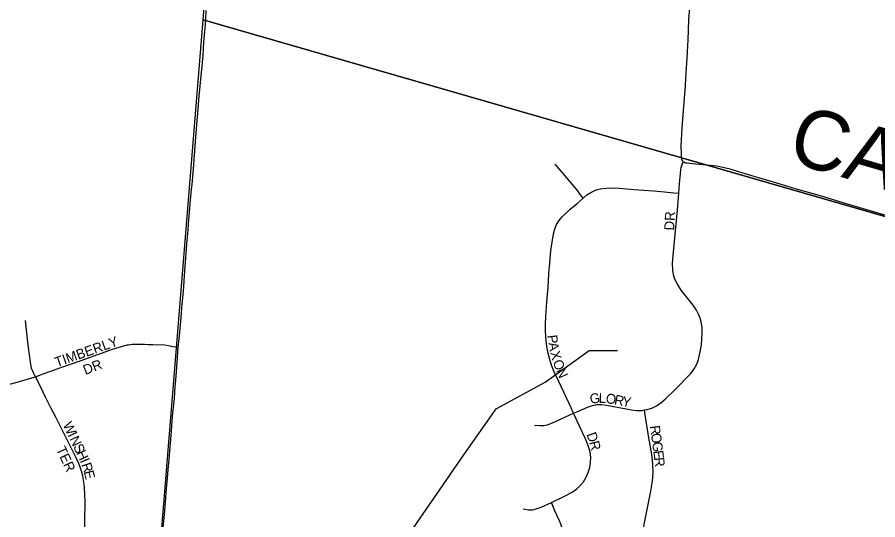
# Model space of a CAD drawing. Extents: x 1410790 to 1770854, y 448063 to 770588.
# Drawn here: x 1520737 to 1525089, y 608740 to 611284 of the extents above; entities that cross this region are included whole.
import ezdxf

# ---------------------------------------------------------------- set-up
doc = ezdxf.new("R2010")
doc.units = 0
for name, color, linetype in [('GM_X_Minor_River', 7, 'Continuous'), ('GM_X_Section', 7, 'Continuous'), ('GM_X_Township_Road', 7, 'Continuous'), ('GM_X_Township_Road_Text', 7, 'Continuous'), ('GM_X_Township_Subdivision', 7, 'Continuous'), ('GM_X_Township_Subdivision_Text', 7, 'Continuous')]:
    doc.layers.add(name, color=color, linetype=linetype)

msp = doc.modelspace()

# ---------------------------------------------------------------- linework, layer by layer
at = {"layer": 'GM_X_Minor_River'}
msp.add_lwpolyline([(1521925.3, 607295.4), (1522055.1, 607382.5), (1522183.3, 607490), (1522235.8, 607615.2), (1522281.7, 607820.8), (1522365.4, 608007.5), (1522448.2, 608148.1), (1522624.2, 608445.1), (1522737.1, 608693.3), (1522994.6, 609068.8), (1523159.3, 609301.8), (1523406.2, 609436.9), (1523629.6, 609596.5), (1523771.8, 609597.4)], dxfattribs=at)
at = {"layer": 'GM_X_Section'}
for points in [[(1522119.9, 616619.5), (1527349.3, 615167.2), (1526943.5, 609749.7), (1521677.3, 611270.6)], [(1526943.5, 609749.7), (1526539, 604404.1), (1521242.6, 605915.5), (1521677.3, 611270.6)]]:
    msp.add_lwpolyline(points, close=True, dxfattribs=at)
at = {"layer": 'GM_X_Township_Road'}
for points in [[(1524104.8, 610551.6), (1524102.3, 610554.8), (1524100.6, 610557.7), (1524098.5, 610563), (1524097.2, 610569.5), (1524096.6, 610575.6), (1524096.1, 610589.1), (1524095.3, 610633.4), (1524100.4, 610723.8), (1524110.8, 610874.7), (1524117, 610936.8), (1524118.4, 610975.3), (1524121.7, 611027), (1524124.5, 611076.9), (1524128.7, 611140.1), (1524130.3, 611167.8), (1524134.1, 611271.7), (1524139.9, 611356.4)], [(1521550.8, 609612.8), (1521556.7, 609670.4), (1521562.3, 609727), (1521565.1, 609761.2), (1521569.4, 609812.7), (1521577, 609897.1), (1521584.2, 610000), (1521596.5, 610155.4), (1521600.5, 610205.6), (1521602.9, 610235.5), (1521612, 610339.7), (1521618.3, 610412.6), (1521620.6, 610437.7), (1521627.9, 610517), (1521638, 610654.7), (1521645.5, 610740), (1521649.6, 610795.9), (1521655.7, 610864.5), (1521661.7, 610936.1), (1521667.9, 611003), (1521676.4, 611089.9), (1521680, 611156.8), (1521686.3, 611230), (1521690.3, 611274), (1521693, 611317)], [(1525130.7, 610280.1), (1525022, 610311.7), (1524918.8, 610342.6), (1524803.8, 610377.4), (1524677.7, 610412.9), (1524634.6, 610426), (1524561, 610448.2), (1524481.3, 610472.4), (1524395.9, 610497.1), (1524342.8, 610513.7), (1524306, 610523.5), (1524274.5, 610529.3), (1524242.2, 610533.6), (1524166.3, 610540.2), (1524123.1, 610544.8), (1524117.4, 610545.6), (1524113, 610546.9), (1524108.1, 610549.4), (1524104.8, 610551.6)], [(1521465.1, 608585.4), (1521469.8, 608636.9), (1521475.5, 608700.9), (1521480.9, 608767), (1521484.6, 608805.1), (1521487.8, 608852.4), (1521490, 608879.6), (1521493.6, 608913.8), (1521499.8, 608992.2), (1521504.9, 609044.4), (1521506.5, 609066.2), (1521508.2, 609087.1), (1521509.4, 609104.9), (1521516.3, 609189.8), (1521520.7, 609241.2), (1521524.2, 609281.9), (1521531.4, 609352.9), (1521533.5, 609383.2), (1521535.6, 609412.2), (1521538, 609446.3), (1521541.4, 609488), (1521545.6, 609538), (1521550.8, 609612.8)]]:
    msp.add_lwpolyline(points, dxfattribs=at)
at = {"layer": 'GM_X_Township_Subdivision'}
for points in [[(1523599.2, 610368.5), (1523581.1, 610391.8), (1523571.1, 610404.7), (1523497, 610491.9), (1523457.5, 610539.9)], [(1524082.5, 610393.1), (1524085.9, 610440.3), (1524090.7, 610492.6), (1524092.8, 610513.1), (1524094.8, 610522.7), (1524098.3, 610533.4), (1524102, 610543.1), (1524104.8, 610551.6)], [(1523599.2, 610368.5), (1523617.9, 610384.8), (1523637.1, 610397.2), (1523661.1, 610407.7), (1523686.4, 610414.7), (1523715.5, 610419), (1523741.6, 610420), (1523780.9, 610418), (1523856.1, 610411.7), (1523954.2, 610405.6), (1524009.6, 610399.9), (1524057.5, 610395.5), (1524082.5, 610393.1)], [(1523909, 609295.9), (1523920.7, 609297.8), (1523945.7, 609305.5), (1523969.4, 609316.7), (1523991.5, 609330.9), (1524014.2, 609349.6), (1524065.7, 609400.2), (1524142.6, 609480.9), (1524160.6, 609504.2), (1524173.4, 609527), (1524182.4, 609551.6), (1524191.2, 609590), (1524196.8, 609625.6), (1524200.2, 609684.4), (1524200.3, 609713.9), (1524198.1, 609731.3), (1524192.3, 609756.9), (1524183, 609781.4), (1524172.1, 609801.6), (1524155.3, 609825.8), (1524095.2, 609902.5), (1524075.4, 609932.7), (1524062.6, 609958.5), (1524057.1, 609973.4), (1524052.4, 610002.4), (1524051.1, 610038.4), (1524053.5, 610077.7), (1524076.5, 610309.4), (1524082.5, 610393.1)], [(1523550.3, 609279.4), (1523538.1, 609305.9), (1523475.3, 609439.5), (1523450.8, 609491.7), (1523438.8, 609521.9), (1523429.6, 609551.5), (1523419.8, 609587.7), (1523413.4, 609630.3), (1523409.6, 609665), (1523408.5, 609699.6), (1523407.9, 609728.8), (1523409.6, 609770.1), (1523415.2, 609842), (1523422.4, 609917.1), (1523425, 609982.7), (1523427.3, 610012.2), (1523428.4, 610018.6), (1523436, 610103.3), (1523448.3, 610187.7), (1523455, 610213), (1523464.2, 610234), (1523476.2, 610253.6), (1523492.9, 610273.7), (1523533.8, 610311.6), (1523567.9, 610341.2), (1523599.2, 610368.5)], [(1520828.3, 609463.5), (1520818.4, 609483.4), (1520813.3, 609494.7), (1520809.6, 609505.1), (1520806.7, 609517.6), (1520803.2, 609537.9), (1520794, 609611.9), (1520789.1, 609654.3), (1520785.5, 609686.3), (1520778, 609747.7)], [(1520828.3, 609463.5), (1520867.9, 609478), (1520906.6, 609491.9), (1520951.6, 609508.3), (1521059.4, 609545.5), (1521162.7, 609583.5), (1521222.9, 609605.4), (1521263.4, 609617.7), (1521292.4, 609624.5), (1521299.2, 609625.7), (1521316.8, 609627.9), (1521325.5, 609628.7), (1521339.3, 609629.4), (1521357.6, 609628.9), (1521381.1, 609628.6), (1521398.7, 609627.6), (1521422.2, 609627.1), (1521483.2, 609624.7), (1521501.5, 609622.6), (1521524.2, 609617.7), (1521539.9, 609614.8), (1521550.8, 609612.8)], [(1520604, 609396), (1520622.5, 609403), (1520638.7, 609408.5), (1520645.3, 609411.1), (1520654, 609414), (1520735.7, 609436.8), (1520799.1, 609454.2), (1520828.3, 609463.5)], [(1521074.5, 608599.9), (1521076.3, 608669.6), (1521078.3, 608719.3), (1521079.2, 608756.1), (1521080, 608811), (1521080, 608825.5), (1521079.7, 608840.8), (1521079.2, 608861.1), (1521076.2, 608907.8), (1521075.5, 608916.3), (1521074, 608929.5), (1521072.2, 608940.2), (1521067.8, 608960.7), (1521061.7, 608985.4), (1521055.3, 609005.7), (1521048, 609025), (1521036.8, 609050.7), (1520979, 609165.2), (1520933, 609256.1), (1520907.2, 609306.4), (1520881.3, 609357.3), (1520853.5, 609414.4), (1520830.1, 609460.1), (1520828.3, 609463.5)], [(1523550.3, 609279.4), (1523566.8, 609286.6), (1523620.8, 609310.3), (1523645.7, 609318.5), (1523668.3, 609322.5), (1523691.1, 609323.3), (1523717.2, 609320.7), (1523842.6, 609295.7), (1523868.7, 609293), (1523894.9, 609293.6), (1523909, 609295.9)], [(1523913, 608193.8), (1523903.3, 608232.9), (1523873.7, 608344), (1523866.8, 608379.5), (1523863, 608418.7), (1523862.5, 608461.3), (1523865.5, 608497.3), (1523875.3, 608555.6), (1523911.1, 608732.7), (1523941.3, 608884.1), (1523949.5, 608935.9), (1523952.7, 608978.5), (1523952, 609017.9), (1523947.5, 609060.3), (1523930.1, 609164), (1523913, 609271), (1523909, 609295.9)], [(1523353.5, 609218.4), (1523380.2, 609216.8), (1523392.2, 609216.8), (1523399.3, 609217.2), (1523407, 609218.3), (1523418.4, 609220.9), (1523430.1, 609225.1), (1523444.5, 609230.6), (1523550.3, 609279.4)], [(1523437.9, 608827.4), (1523505, 608859.7), (1523542.5, 608880), (1523566.7, 608896.9), (1523586, 608914.7), (1523600.4, 608932.5), (1523614, 608955), (1523624.6, 608979), (1523632.3, 609004.1), (1523636.4, 609030), (1523636.8, 609056.2), (1523633.6, 609082.2), (1523626.4, 609110.9), (1523610.6, 609149.6), (1523579.2, 609216.8), (1523550.3, 609279.4)], [(1523295.8, 608794.6), (1523322.6, 608790.2), (1523342.2, 608790.9), (1523356.1, 608793.6), (1523386.3, 608803.8), (1523437.9, 608827.4)], [(1523438, 608303.2), (1523483.8, 608378.7), (1523499.1, 608410.7), (1523507.4, 608435), (1523511.9, 608456.9), (1523514.1, 608482.4), (1523514.6, 608596.9), (1523511.7, 608629.1), (1523505.5, 608660.8), (1523495.1, 608694.8), (1523479.4, 608734.1), (1523455.4, 608785.5), (1523437.9, 608827.4)]]:
    msp.add_lwpolyline(points, dxfattribs=at)

# ---------------------------------------------------------------- texts
at = {"layer": 'GM_X_Township_Road_Text'}
msp.add_text('CARPENTER', height=300, rotation=343.6093, dxfattribs=at).set_placement((1524621.9, 610557.6))
at = {"layer": 'GM_X_Township_Subdivision_Text'}
for s, rotation, p in [('DR', 86.989, (1524058.5, 610203.3)), ('TIMBERLY', 19.4395, (1520936.6, 609511.5)), ('P', 276.393, (1523417.4, 609673.3)), ('A', 280.7697, (1523421.9, 609634.2)), ('X', 285.0374, (1523431, 609587)), ('DR', 21.2508, (1521081.3, 609472.3)), ('O', 290.2016, (1523444, 609539.9)), ('N', 294.3595, (1523460.6, 609494.9)), ('G', 5.516, (1523634.7, 609327.6)), ('L', 358.9345, (1523677, 609331.8)), ('O', 351.0245, (1523710.4, 609331.3)), ('R', 348.6329, (1523753.3, 609324.5)), ('Y', 348.4693, (1523792.1, 609316.7)), ('W', 295.3922, (1520965.6, 609221.3)), ('R', 277.6372, (1523936.4, 609214.2)), ('I', 295.3919, (1520990.1, 609169.6)), ('N', 295.4016, (1520999.5, 609149.7)), ('D', 289.8729, (1523614.6, 609172.4)), ('O', 277.6293, (1523941.6, 609175)), ('TER', 294.6245, (1520932.3, 609097.7)), ('S', 295.3977, (1521018.4, 609110)), ('R', 284.8845, (1523629.2, 609132.2)), ('G', 277.6293, (1523947.5, 609131.4)), ('H', 295.3919, (1521033.5, 609078.2)), ('E', 277.6299, (1523953.3, 609087.8)), ('I', 292.6333, (1521052.1, 609039)), ('R', 288.2698, (1521060.2, 609019.6)), ('R', 276.3992, (1523958, 609053.2)), ('E', 284.414, (1521072.4, 608982.9))]:
    msp.add_text(s, height=50, rotation=rotation, dxfattribs=at).set_placement(p)

doc.saveas('drawing.dxf')
